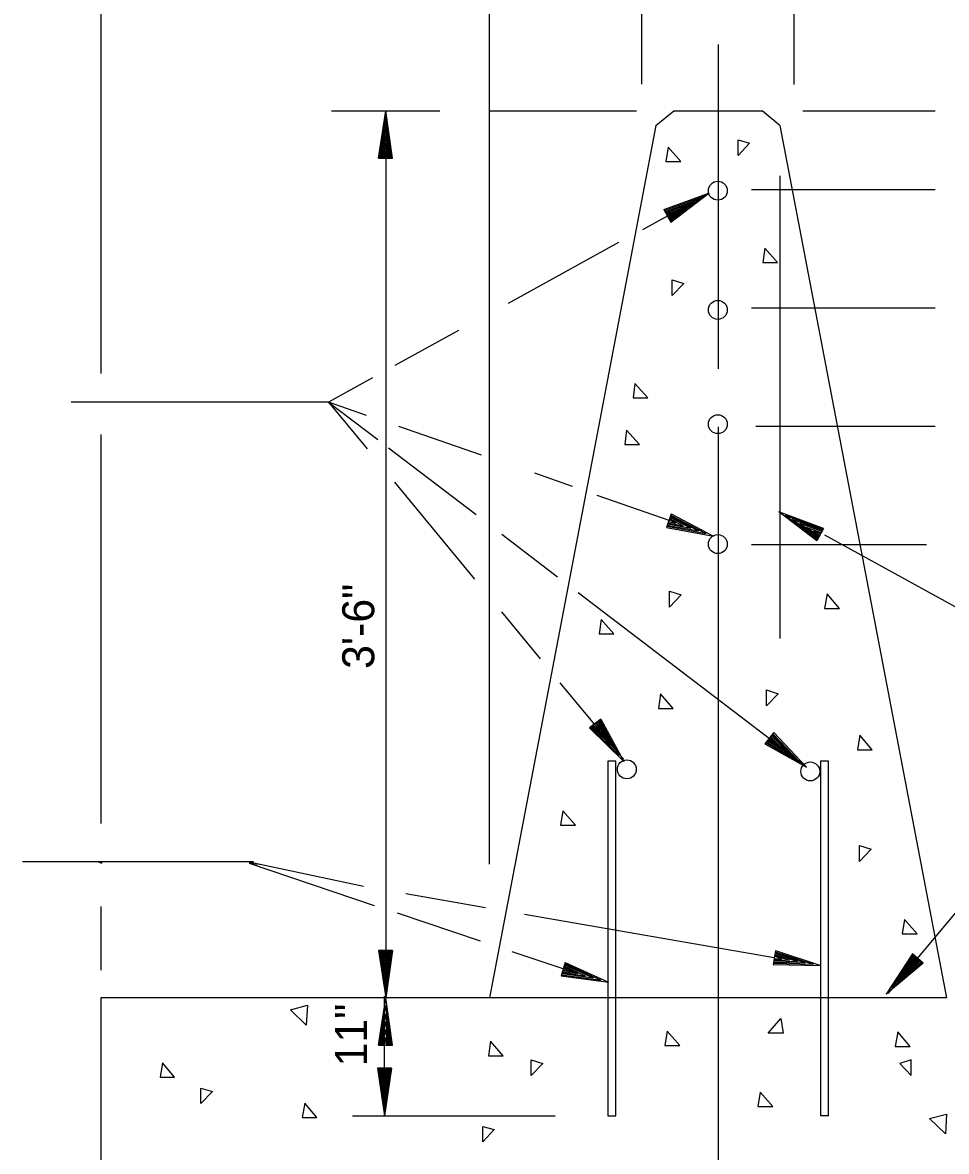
# Model space of a CAD drawing. Extents: x 714919 to 718439, y 1619644 to 1621844.
# Drawn here: x 715504.9 to 715804.4, y 1621100.6 to 1621466.5 of the extents above; entities that cross this region are included whole.
import ezdxf

# ---------------------------------------------------------------- set-up
doc = ezdxf.new("R2010")
doc.units = 0
for name, color, linetype in [('R_Centerline', 7, 'Continuous'), ('R_Dimension', 7, 'Continuous'), ('T_Drafting', 7, 'Continuous')]:
    doc.layers.add(name, color=color, linetype=linetype)

msp = doc.modelspace()

# ---------------------------------------------------------------- linework, layer by layer
at = {"layer": 'R_Centerline'}
for p, q in [((715730.36, 1621459.34), (715730.36, 1621354.19)), ((715730.36, 1621335.44), (715730.36, 1621073.04))]:
    msp.add_line(p, q, dxfattribs=at)
at = {"layer": 'R_Dimension'}
for p, q in [((715530.22, 1621561.2), (715530.22, 1621352.71)), ((715656.14, 1621529.75), (715656.14, 1621193.74)), ((715705.56, 1621487.07), (715705.56, 1621446.55)), ((715754.98, 1621486.9), (715754.98, 1621446.38)), ((715605.08, 1621437.91), (715640.16, 1621437.91)), ((715620.29, 1621422.53), (715622.62, 1621437.91)), ((715620.72, 1621422.53), (715622.62, 1621435.4)), ((715622.62, 1621437.91), (715622.62, 1621265.89)), ((715624.86, 1621422.53), (715622.62, 1621437.91)), ((715624.52, 1621422.53), (715622.62, 1621435.4)), ((715656.31, 1621437.91), (715703.92, 1621437.91)), ((715757.83, 1621437.91), (715800.77, 1621437.91)), ((715621.06, 1621422.53), (715622.62, 1621432.64)), ((715624.09, 1621422.53), (715622.62, 1621432.64)), ((715621.41, 1621422.53), (715622.62, 1621430.13)), ((715623.74, 1621422.53), (715622.62, 1621430.13)), ((715621.84, 1621422.53), (715622.62, 1621427.54)), ((715622.19, 1621422.53), (715622.62, 1621425.04)), ((715623.4, 1621422.53), (715622.62, 1621427.54)), ((715622.96, 1621422.53), (715622.62, 1621425.04)), ((715620.29, 1621422.53), (715624.86, 1621422.53)), ((715750.4, 1621416.83), (715750.4, 1621266.84)), ((715727.42, 1621411.21), (715705.82, 1621399.29)), ((715712.82, 1621405.85), (715727.42, 1621411.21)), ((715713.08, 1621405.6), (715725.17, 1621410)), ((715714.89, 1621402.14), (715725.17, 1621410)), ((715715.07, 1621401.79), (715727.42, 1621411.21)), ((715741.25, 1621412.33), (715800.77, 1621412.33)), ((715713.25, 1621405.16), (715722.84, 1621408.71)), ((715713.42, 1621404.82), (715720.6, 1621407.5)), ((715713.6, 1621404.47), (715718.35, 1621406.2)), ((715714.29, 1621403.18), (715718.35, 1621406.2)), ((715714.55, 1621402.83), (715720.6, 1621407.5)), ((715714.72, 1621402.49), (715722.84, 1621408.71)), ((715712.82, 1621405.85), (715715.07, 1621401.79)), ((715713.77, 1621404.21), (715716.02, 1621404.99)), ((715714.12, 1621403.52), (715716.02, 1621404.99)), ((715698.13, 1621395.14), (715662.28, 1621375.44)), ((715741.25, 1621374.06), (715800.77, 1621374.06)), ((715646.21, 1621366.63), (715625.56, 1621355.31)), ((715618.3, 1621351.34), (715604.04, 1621343.47)), ((715530.54, 1621343.47), (715520.61, 1621343.47)), ((715604.04, 1621343.47), (715529.45, 1621343.47)), ((715616.4, 1621339.15), (715604.04, 1621343.47)), ((715604.04, 1621343.47), (715616.57, 1621328.35)), ((715604.04, 1621343.47), (715620.03, 1621331.29)), ((715530.22, 1621332.95), (715530.22, 1621238.23)), ((715653.72, 1621326.28), (715626.85, 1621335.53)), ((715742.63, 1621335.7), (715754.21, 1621335.7)), ((715749.11, 1621335.7), (715800.77, 1621335.7)), ((715623.48, 1621328.61), (715651.91, 1621307.01)), ((715683.18, 1621316.09), (715670.92, 1621320.41)), ((715625.47, 1621317.47), (715651.39, 1621286.02)), ((715714.89, 1621304.94), (715691.22, 1621313.23)), ((715715.15, 1621307.27), (715713.6, 1621302.87)), ((715715.15, 1621307.27), (715728.89, 1621300.01)), ((715764.57, 1621302.52), (715750.06, 1621307.88)), ((715762.41, 1621298.46), (715750.06, 1621307.88)), ((715714.03, 1621303.99), (715721.55, 1621302.61)), ((715714.12, 1621304.33), (715719.04, 1621303.38)), ((715714.2, 1621304.77), (715716.71, 1621304.25)), ((715714.46, 1621305.37), (715716.71, 1621304.25)), ((715714.63, 1621305.72), (715719.04, 1621303.38)), ((715714.72, 1621306.15), (715721.55, 1621302.61)), ((715714.81, 1621306.49), (715723.97, 1621301.74)), ((715714.98, 1621306.84), (715726.38, 1621300.88)), ((715764.31, 1621302.17), (715752.22, 1621306.67)), ((715762.5, 1621298.81), (715752.22, 1621306.67)), ((715762.76, 1621299.15), (715754.55, 1621305.37)), ((715764.23, 1621301.83), (715754.55, 1621305.37)), ((715763.97, 1621301.48), (715756.88, 1621304.08)), ((715762.93, 1621299.5), (715756.88, 1621304.08)), ((715660.29, 1621300.62), (715678.35, 1621286.88)), ((715713.6, 1621302.87), (715728.89, 1621300.01)), ((715713.77, 1621303.3), (715726.38, 1621300.88)), ((715713.86, 1621303.56), (715723.97, 1621301.74)), ((715763.1, 1621299.84), (715759.04, 1621302.87)), ((715763.8, 1621301.14), (715759.04, 1621302.87)), ((715763.28, 1621300.19), (715761.38, 1621301.66)), ((715763.71, 1621300.79), (715761.38, 1621301.66)), ((715764.57, 1621302.52), (715762.41, 1621298.46)), ((715764.83, 1621300.45), (715841.47, 1621258.28)), ((715741.25, 1621297.34), (715752.91, 1621297.34)), ((715752.3, 1621297.34), (715797.92, 1621297.34)), ((715685, 1621281.78), (715758.44, 1621225.8)), ((715660.2, 1621275.48), (715672.73, 1621260.27)), ((715622.62, 1621265.89), (715622.62, 1621150.37)), ((715679.12, 1621252.49), (715699.69, 1621227.61)), ((715530.22, 1621238.23), (715530.22, 1621206.88)), ((715692.34, 1621240.66), (715688.71, 1621237.89)), ((715688.71, 1621237.89), (715699.77, 1621227.01)), ((715688.97, 1621238.15), (715698.22, 1621229.08)), ((715689.32, 1621238.24), (715696.66, 1621231.15)), ((715689.58, 1621238.5), (715695.02, 1621233.23)), ((715689.92, 1621238.67), (715693.55, 1621235.3)), ((715690.18, 1621239.02), (715692, 1621237.29)), ((715690.79, 1621239.45), (715692, 1621237.29)), ((715691.05, 1621239.62), (715693.55, 1621235.3)), ((715691.48, 1621239.88), (715695.02, 1621233.23)), ((715691.74, 1621240.14), (715696.66, 1621231.15)), ((715692.08, 1621240.4), (715698.22, 1621229.08)), ((715692.34, 1621240.66), (715699.77, 1621227.01)), ((715748.42, 1621236.34), (715745.57, 1621232.71)), ((715746.69, 1621234.26), (715748.85, 1621233.05)), ((715747.21, 1621234.87), (715748.85, 1621233.05)), ((715747.38, 1621235.13), (715750.84, 1621231.41)), ((715747.64, 1621235.39), (715752.91, 1621229.86)), ((715747.9, 1621235.73), (715754.9, 1621228.3)), ((715748.16, 1621235.99), (715756.97, 1621226.66)), ((715748.42, 1621236.34), (715759.04, 1621225.11)), ((715745.57, 1621232.71), (715759.04, 1621225.11)), ((715745.82, 1621233.05), (715756.97, 1621226.66)), ((715745.91, 1621233.31), (715754.9, 1621228.3)), ((715746.26, 1621233.66), (715752.91, 1621229.86)), ((715746.52, 1621234.01), (715750.84, 1621231.41)), ((715827.9, 1621202.64), (715785.4, 1621151.75)), ((715504.88, 1621194.52), (715579.71, 1621194.52)), ((715529.16, 1621194.52), (715530.54, 1621194.05)), ((715529.34, 1621194.52), (715530.54, 1621194.15)), ((715529.34, 1621194.52), (715530.54, 1621194.32)), ((715530.03, 1621194.52), (715530.54, 1621194.41)), ((715578.37, 1621194.41), (715615.45, 1621186.57)), ((715578.37, 1621194.32), (715581.84, 1621193.74)), ((715578.37, 1621194.15), (715580.8, 1621193.4)), ((715578.37, 1621194.05), (715618.82, 1621180.26)), ((715629.1, 1621184.15), (715655.02, 1621179.66)), ((715530.22, 1621180.01), (715530.22, 1621159.34)), ((715626.33, 1621177.93), (715653.29, 1621168.86)), ((715667.63, 1621177.5), (715748.59, 1621163.42)), ((715620.29, 1621165.75), (715622.62, 1621150.37)), ((715624.86, 1621165.75), (715620.29, 1621165.75)), ((715620.29, 1621165.75), (715622.62, 1621150.37)), ((715624.86, 1621165.75), (715620.29, 1621165.75)), ((715620.72, 1621165.75), (715622.62, 1621152.96)), ((715620.72, 1621165.75), (715622.62, 1621152.96)), ((715621.06, 1621165.75), (715622.62, 1621155.64)), ((715621.06, 1621165.75), (715622.62, 1621155.64)), ((715621.41, 1621165.75), (715622.62, 1621158.15)), ((715621.41, 1621165.75), (715622.62, 1621158.15)), ((715621.84, 1621165.75), (715622.62, 1621160.74)), ((715621.84, 1621165.75), (715622.62, 1621160.74)), ((715622.19, 1621165.75), (715622.62, 1621163.24)), ((715622.19, 1621165.75), (715622.62, 1621163.24)), ((715624.86, 1621165.75), (715622.62, 1621150.37)), ((715623.4, 1621165.75), (715622.62, 1621160.74)), ((715624.09, 1621165.75), (715622.62, 1621155.64)), ((715624.52, 1621165.75), (715622.62, 1621152.96)), ((715623.74, 1621165.75), (715622.62, 1621158.15)), ((715622.96, 1621165.75), (715622.62, 1621163.24)), ((715624.86, 1621165.75), (715622.62, 1621150.37)), ((715623.4, 1621165.75), (715622.62, 1621160.74)), ((715624.09, 1621165.75), (715622.62, 1621155.64)), ((715624.52, 1621165.75), (715622.62, 1621152.96)), ((715623.74, 1621165.75), (715622.62, 1621158.15)), ((715622.96, 1621165.75), (715622.62, 1621163.24)), ((715663.49, 1621165.4), (715684.22, 1621158.49)), ((715749.02, 1621165.75), (715748.24, 1621161.17)), ((715748.85, 1621164.97), (715758.61, 1621161.69)), ((715748.93, 1621165.32), (715761.2, 1621161.26)), ((715749.02, 1621165.75), (715763.71, 1621160.82)), ((715793.43, 1621164.63), (715784.88, 1621151.58)), ((715796.89, 1621161.6), (715793.43, 1621164.63)), ((715680.77, 1621161.86), (715679.47, 1621157.54)), ((715680.51, 1621161.17), (715689.84, 1621156.85)), ((715680.68, 1621161.52), (715692.34, 1621156.07)), ((715680.77, 1621161.86), (715694.85, 1621155.47)), ((715748.24, 1621161.17), (715763.71, 1621160.82)), ((715748.33, 1621161.6), (715761.2, 1621161.26)), ((715748.42, 1621162.38), (715756.11, 1621162.12)), ((715748.42, 1621161.95), (715758.61, 1621161.69)), ((715748.5, 1621162.73), (715753.51, 1621162.55)), ((715748.59, 1621163.07), (715751.01, 1621163.07)), ((715748.76, 1621164.19), (715753.51, 1621162.55)), ((715748.76, 1621163.85), (715751.01, 1621163.07)), ((715748.85, 1621164.54), (715756.11, 1621162.12)), ((715796.89, 1621161.6), (715784.88, 1621151.58)), ((715793.78, 1621164.37), (715786.61, 1621153.57)), ((715796.54, 1621161.77), (715786.61, 1621153.57)), ((715793.95, 1621164.11), (715788.33, 1621155.55)), ((715796.28, 1621162.03), (715788.33, 1621155.55)), ((715794.29, 1621163.85), (715790.06, 1621157.45)), ((715795.94, 1621162.38), (715790.06, 1621157.45)), ((715794.55, 1621163.59), (715791.79, 1621159.36)), ((715795.68, 1621162.55), (715791.79, 1621159.36)), ((715794.81, 1621163.33), (715793.52, 1621161.26)), ((715795.42, 1621162.81), (715793.52, 1621161.26)), ((715679.47, 1621157.54), (715694.85, 1621155.47)), ((715679.64, 1621157.8), (715692.34, 1621156.07)), ((715679.81, 1621158.58), (715687.33, 1621157.54)), ((715679.81, 1621158.23), (715689.84, 1621156.85)), ((715679.9, 1621158.92), (715684.91, 1621158.23)), ((715680.07, 1621159.36), (715682.49, 1621158.92)), ((715680.25, 1621160.05), (715682.49, 1621158.92)), ((715680.42, 1621160.39), (715684.91, 1621158.23)), ((715680.51, 1621160.74), (715687.33, 1621157.54)), ((715620.29, 1621135.08), (715622.62, 1621150.37)), ((715620.29, 1621135.08), (715622.62, 1621150.37)), ((715622.19, 1621112.18), (715622.19, 1621150.97)), ((715624.86, 1621135.08), (715622.62, 1621150.37)), ((715624.86, 1621135.08), (715622.62, 1621150.37)), ((715620.72, 1621135.08), (715622.62, 1621147.86)), ((715620.72, 1621135.08), (715622.62, 1621147.86)), ((715624.52, 1621135.08), (715622.62, 1621147.86)), ((715624.52, 1621135.08), (715622.62, 1621147.86)), ((715621.06, 1621135.08), (715622.62, 1621145.19)), ((715621.06, 1621135.08), (715622.62, 1621145.19)), ((715621.41, 1621135.08), (715622.62, 1621142.68)), ((715621.41, 1621135.08), (715622.62, 1621142.68)), ((715624.09, 1621135.08), (715622.62, 1621145.19)), ((715624.09, 1621135.08), (715622.62, 1621145.19)), ((715623.74, 1621135.08), (715622.62, 1621142.68)), ((715623.74, 1621135.08), (715622.62, 1621142.68)), ((715621.84, 1621135.08), (715622.62, 1621140.09)), ((715621.84, 1621135.08), (715622.62, 1621140.09)), ((715623.4, 1621135.08), (715622.62, 1621140.09)), ((715623.4, 1621135.08), (715622.62, 1621140.09)), ((715622.19, 1621135.08), (715622.62, 1621137.5)), ((715622.19, 1621135.08), (715622.62, 1621137.5)), ((715622.96, 1621135.08), (715622.62, 1621137.5)), ((715622.96, 1621135.08), (715622.62, 1621137.5)), ((715620.29, 1621135.08), (715624.86, 1621135.08)), ((715620.29, 1621135.08), (715624.86, 1621135.08)), ((715619.94, 1621127.56), (715622.19, 1621112.18)), ((715624.52, 1621127.56), (715619.94, 1621127.56)), ((715620.29, 1621127.56), (715622.19, 1621114.77)), ((715620.72, 1621127.56), (715622.19, 1621117.45)), ((715621.06, 1621127.56), (715622.19, 1621119.96)), ((715621.41, 1621127.56), (715622.19, 1621122.55)), ((715621.84, 1621127.56), (715622.19, 1621125.05)), ((715624.52, 1621127.56), (715622.19, 1621112.18)), ((715622.96, 1621127.56), (715622.19, 1621122.55)), ((715623.74, 1621127.56), (715622.19, 1621117.45)), ((715624.09, 1621127.56), (715622.19, 1621114.77)), ((715623.4, 1621127.56), (715622.19, 1621119.96)), ((715622.62, 1621127.56), (715622.19, 1621125.05)), ((715611.9, 1621112.18), (715677.57, 1621112.18))]:
    msp.add_line(p, q, dxfattribs=at)
at = {"layer": 'T_Drafting'}
for p, q in [((715710.23, 1621433.07), (715716.02, 1621437.91)), ((715716.02, 1621437.91), (715744.7, 1621437.91)), ((715750.4, 1621433.07), (715744.7, 1621437.91)), ((715710.23, 1621433.07), (715691.57, 1621335.44)), ((715750.4, 1621433.07), (715804.4, 1621150.37)), ((715736.84, 1621423.39), (715736.84, 1621428.49)), ((715736.84, 1621428.49), (715740.55, 1621427.37)), ((715714.2, 1621426.07), (715713.42, 1621421.41)), ((715718.26, 1621421.41), (715714.2, 1621426.07)), ((715740.55, 1621427.37), (715736.84, 1621423.39)), ((715713.42, 1621421.41), (715718.26, 1621421.41)), ((715745.48, 1621393.33), (715744.87, 1621388.66)), ((715749.63, 1621388.66), (715745.48, 1621393.33)), ((715744.87, 1621388.66), (715749.63, 1621388.66)), ((715715.5, 1621378.03), (715715.5, 1621383.13)), ((715715.5, 1621383.13), (715719.3, 1621381.92)), ((715719.3, 1621381.92), (715715.5, 1621378.03)), ((715703.4, 1621349.52), (715702.8, 1621344.86)), ((715707.55, 1621344.86), (715703.4, 1621349.52)), ((715702.8, 1621344.86), (715707.55, 1621344.86)), ((715691.57, 1621335.44), (715656.23, 1621150.37)), ((715700.72, 1621334.32), (715700.12, 1621329.74)), ((715704.87, 1621329.74), (715700.72, 1621334.32)), ((715700.12, 1621329.74), (715704.87, 1621329.74)), ((715714.63, 1621277.03), (715714.63, 1621282.13)), ((715714.63, 1621282.13), (715718.35, 1621281.01)), ((715718.35, 1621281.01), (715714.63, 1621277.03)), ((715765.7, 1621281.27), (715764.92, 1621276.6)), ((715769.76, 1621276.6), (715765.7, 1621281.27)), ((715764.92, 1621276.6), (715769.76, 1621276.6)), ((715692.52, 1621272.97), (715691.82, 1621268.39)), ((715696.58, 1621268.39), (715692.52, 1621272.97)), ((715691.82, 1621268.39), (715696.58, 1621268.39)), ((715711.7, 1621248.95), (715711.01, 1621244.2)), ((715715.76, 1621244.2), (715711.7, 1621248.95)), ((715746.08, 1621245.06), (715746.08, 1621250.16)), ((715746.08, 1621250.16), (715749.89, 1621248.95)), ((715749.89, 1621248.95), (715746.08, 1621245.06)), ((715711.01, 1621244.2), (715715.76, 1621244.2)), ((715776.32, 1621235.47), (715775.55, 1621230.81)), ((715780.38, 1621230.81), (715776.32, 1621235.47)), ((715775.55, 1621230.81), (715780.38, 1621230.81)), ((715694.59, 1621227.09), (715694.59, 1621112.18)), ((715697.18, 1621227.09), (715694.59, 1621227.09)), ((715697.18, 1621112.18), (715697.18, 1621227.09)), ((715766.21, 1621227.09), (715763.62, 1621227.09)), ((715763.62, 1621227.09), (715763.62, 1621112.18)), ((715766.21, 1621112.18), (715766.21, 1621227.09)), ((715680.07, 1621211.02), (715679.3, 1621206.36)), ((715684.13, 1621206.36), (715680.07, 1621211.02)), ((715679.3, 1621206.36), (715684.13, 1621206.36)), ((715776.24, 1621194.61), (715776.24, 1621199.7)), ((715776.24, 1621199.7), (715780.04, 1621198.58)), ((715780.04, 1621198.58), (715776.24, 1621194.61)), ((715790.84, 1621175.77), (715790.06, 1621171.11)), ((715794.9, 1621171.11), (715790.84, 1621175.77)), ((715790.06, 1621171.11), (715794.9, 1621171.11)), ((715656.23, 1621150.37), (715530.22, 1621150.37)), ((715530.22, 1621150.37), (715530.22, 1621065.62)), ((715804.4, 1621150.37), (715656.23, 1621150.37)), ((715591.77, 1621146.48), (715597.3, 1621148.04)), ((715596.87, 1621141.47), (715591.77, 1621146.48)), ((715597.3, 1621148.04), (715596.87, 1621141.47)), ((715746.6, 1621138.97), (715750.75, 1621143.63)), ((715750.75, 1621143.63), (715751.44, 1621138.97)), ((715713.86, 1621139.57), (715713.08, 1621134.9)), ((715717.92, 1621134.9), (715713.86, 1621139.57)), ((715751.44, 1621138.97), (715746.6, 1621138.97)), ((715788.68, 1621139.31), (715787.81, 1621134.65)), ((715792.65, 1621134.65), (715788.68, 1621139.31)), ((715656.57, 1621136.29), (715655.97, 1621131.62)), ((715660.72, 1621131.62), (715656.57, 1621136.29)), ((715713.08, 1621134.9), (715717.92, 1621134.9)), ((715787.81, 1621134.65), (715792.65, 1621134.65)), ((715550.22, 1621129.33), (715549.44, 1621124.67)), ((715554.19, 1621124.67), (715550.22, 1621129.33)), ((715655.97, 1621131.62), (715660.72, 1621131.62)), ((715669.79, 1621125.23), (715669.79, 1621130.24)), ((715669.79, 1621130.24), (715673.51, 1621129.12)), ((715673.51, 1621129.12), (715669.79, 1621125.23)), ((715793, 1621130.24), (715789.28, 1621129.12)), ((715789.28, 1621129.12), (715793, 1621125.23)), ((715793, 1621125.23), (715793, 1621130.24)), ((715549.44, 1621124.67), (715554.19, 1621124.67)), ((715562.7, 1621116.09), (715562.7, 1621121.1)), ((715562.7, 1621121.1), (715566.5, 1621120.06)), ((715566.5, 1621120.06), (715562.7, 1621116.09)), ((715744.01, 1621119.78), (715743.23, 1621115.12)), ((715748.16, 1621115.12), (715744.01, 1621119.78)), ((715596.35, 1621116.24), (715595.57, 1621111.58)), ((715600.33, 1621111.58), (715596.35, 1621116.24)), ((715743.23, 1621115.12), (715748.16, 1621115.12)), ((715595.57, 1621111.58), (715600.33, 1621111.58)), ((715694.59, 1621112.18), (715697.18, 1621112.18)), ((715766.21, 1621112.18), (715763.62, 1621112.18)), ((715798.87, 1621111.32), (715804.4, 1621112.7)), ((715804.06, 1621106.31), (715798.87, 1621111.32)), ((715804.4, 1621112.7), (715804.06, 1621106.31)), ((715654.07, 1621103.71), (715654.07, 1621108.73)), ((715654.07, 1621108.73), (715657.78, 1621107.69)), ((715657.78, 1621107.69), (715654.07, 1621103.71))]:
    msp.add_line(p, q, dxfattribs=at)
for centre in [(715730.29, 1621411.97), (715730.29, 1621373.33), (715730.29, 1621336.3), (715730.29, 1621297.43), (715700.78, 1621224.44), (715760.27, 1621223.75)]:
    msp.add_circle(centre, 3.07, dxfattribs=at)

# ---------------------------------------------------------------- texts
at = {"layer": 'R_Dimension'}
for s, p in [('3\'-6"', (715618.9, 1621256.99)), ('11"', (715616.57, 1621128.16))]:
    msp.add_text(s, height=10.369, rotation=90, dxfattribs=at).set_placement(p)

doc.saveas('drawing.dxf')
